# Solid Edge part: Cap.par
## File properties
Author: Deepak Maini
Template: Normal.par
Last saved by: CADCIM
Revision: 6
Application: Solid Edge
Accuracy: 0.99
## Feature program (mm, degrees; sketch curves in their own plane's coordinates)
sketch for "unnamed Protrusion 1" plane through (0, 0, 0) normal (0, -1, 0) x-axis (1, 0, 0)
  line (-54, 0) -> (-54, 12)
  line (-54, 12) -> (-31.749, 12)
  arc centre (0, -24) radius 48 from (-31.749, 12) to (31.749, 12) cw
  line (31.749, 12) -> (54, 12)
  line (54, 12) -> (54, 0)
  line (54, 0) -> (27.6274, 0)
  line (27.6274, -16) -> (27.6274, 0)
  line (22.6274, -16) -> (27.6274, -16)
  arc centre (0, -24) radius 24 from (-22.6274, -16) to (22.6274, -16) cw
  line (-27.6274, -16) -> (-22.6274, -16)
  line (-27.6274, 0) -> (-27.6274, -16)
  line (-27.6274, 0) -> (-54, 0)
  dimension (linear) = 54
extrude "unnamed Protrusion 1" add finite 46 symmetric
sketch for "Hole_1" plane through (42.8745, 0, 12) normal (0, 0, 1) x-axis (0, 1, 0)
hole "Hole_1" diameter 12 through
sketch for "unnamed Cutout 1" plane through (42.8745, 0, 12) normal (0, 0, 1) x-axis (0, 1, 0)
extrude "unnamed Cutout 1" cut through along +normal
sketch for "unnamed Cutout 2" plane through (38, 0, 12) normal (0, 0, 1) x-axis (0, 1, 0)
  line (-23, -16) -> (-23, -10.8569)
  arc centre (0, 38) radius 54 from (23, -10.8569) to (-23, -10.8569) cw
  line (23, -16) -> (23, -10.8569)
  line (1.0714, -23.7143) -> (23, -16)
  line (-23, -16) -> (1.0714, -23.7143)
extrude "unnamed Cutout 2" cut through along -normal
mirror "unnamed Mirror 1" of "unnamed Cutout 2", "unnamed Cutout 1", "Hole_1" about plane through (0, 0, 0) normal (1, 0, 0)
hole "unnamed Hole 1" through
extrude "unnamed Cutout 3" cut through
extrude "unnamed Cutout 4" cut through
sketch for "Hole_3" plane through (25.1274, 0, 24) normal (0, 0, -1) x-axis (0, 1, 0)
  hole centre (0, -25.1274) bore radius 3
hole "Hole_3" diameter 6 through  Plane_Distance = 40 mm; CounterBoreDepth = 16 mm
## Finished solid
Body 1: solid body, 21 faces, 50 edges, 28 vertices.
  Faces by surface: plane 11, cylinder 10
  Edges by curve: line 30, circle 16, intersection 4
Bounding box of the edges (mm): 108.000 x 46.000 x 40.000, from (-54, -23, -16) to (54, 23, 24).
Cylindrical faces by radius (mm): R3 x1, R4 x1, R6 x2, R17 x2, R24 x1, R48 x1, R54 x2
Planar faces by outward normal: +x 1, +y 1, +z 3, -x 1, -y 1, -z 4
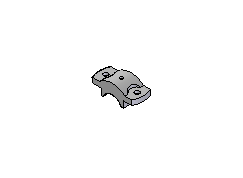
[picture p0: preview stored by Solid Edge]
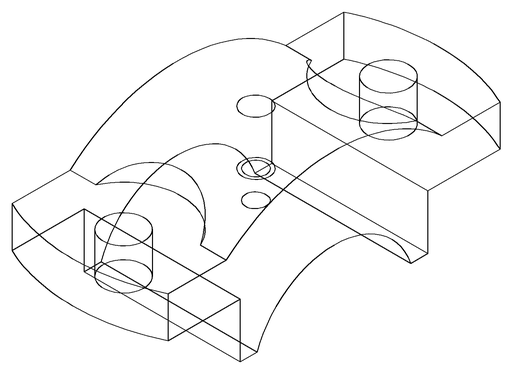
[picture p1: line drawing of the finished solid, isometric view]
